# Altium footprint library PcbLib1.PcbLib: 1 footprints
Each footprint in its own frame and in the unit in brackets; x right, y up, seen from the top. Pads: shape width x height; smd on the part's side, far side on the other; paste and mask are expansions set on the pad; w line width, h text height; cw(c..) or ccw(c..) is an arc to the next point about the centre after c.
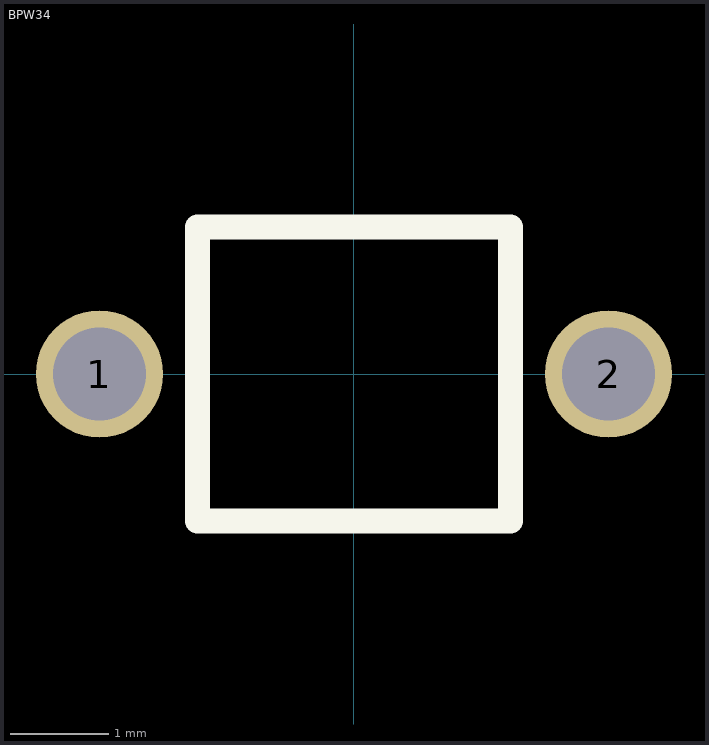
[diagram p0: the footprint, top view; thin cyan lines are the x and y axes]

## BPW34 [mm]
pads (2):
  round 1.3 hole 0.95: 1(-2.6,0) 2(2.6,0)
Top Overlay:
  lines w0.254: -1.6,-1.5 1.6,-1.5 1.6,1.5 -1.6,1.5 -1.6,-1.5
